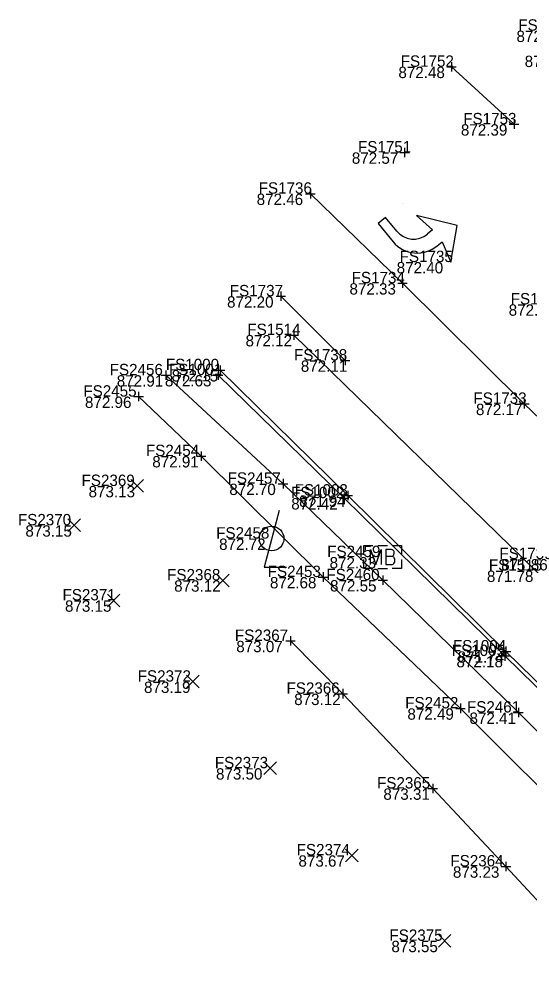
# Model space of a CAD drawing. Extents: x 1479420 to 1479833, y 379731 to 380103.
# Drawn here: x 1479444.2 to 1479498.2, y 379987.2 to 380088.3 of the extents above; entities that cross this region are included whole.
import ezdxf

# ---------------------------------------------------------------- set-up
doc = ezdxf.new("R2010")
doc.units = 0
for name, color, linetype in [('LT_X_Poles', 7, 'Continuous'), ('PM_X_Cells', 7, 'Continuous'), ('PM_X_Channelizing_Line', 7, 'Continuous'), ('PM_X_Lane_Line', 7, 'Continuous'), ('PV_X_Curb', 7, 'Continuous'), ('PV_X_Walk', 7, 'Continuous'), ('RD_X_Cells', 7, 'Continuous'), ('SV_X_Break_Lines', 7, 'Continuous'), ('SV_X_Random_Point', 7, 'Continuous'), ('SV_X_Shot_Marker', 7, 'Continuous'), ('SV_X_Text_Elevation', 7, 'Continuous'), ('SV_X_Text_Name', 7, 'Continuous'), ('UT_X_Water', 7, 'Continuous')]:
    doc.layers.add(name, color=color, linetype=linetype)

msp = doc.modelspace()

# ---------------------------------------------------------------- linework, layer by layer
at = {"layer": 'LT_X_Poles'}
msp.add_lwpolyline([(1479471.67, 380036.31), (1479470.09, 380030.33), (1479472.46, 380030.33)], dxfattribs=at)
msp.add_circle((1479470.88, 380033.36), 1.3, dxfattribs=at)
at = {"layer": 'PM_X_Cells'}
for p, q in [((1479484.71, 380068.78), (1479484.71, 380068.78)), ((1479482.91, 380067.3), (1479482.14, 380066.67)), ((1479484.09, 380065.86), (1479482.91, 380067.3)), ((1479490.48, 380066.48), (1479486.19, 380067.51)), ((1479486.19, 380067.51), (1479487.87, 380065.99)), ((1479482.14, 380066.67), (1479483.71, 380064.75)), ((1479489.79, 380062.6), (1479490.48, 380066.48)), ((1479487.87, 380065.99), (1479487.32, 380065.55)), ((1479488.37, 380064.33), (1479488.88, 380064.75)), ((1479488.88, 380064.75), (1479489.79, 380062.6)), ((1479489.79, 380062.6), (1479489.79, 380062.6))]:
    msp.add_line(p, q, dxfattribs=at)
for centre, radius, end in [((1479485.87, 380067.32), 2.3, 309.3649), ((1479486.25, 380066.83), 3.28, 310.2733)]:
    msp.add_arc(centre, radius, 219.3649, end, dxfattribs=at)
at = {"layer": 'PM_X_Channelizing_Line'}
msp.add_lwpolyline([(1479582.67, 379963.81), (1479570.27, 379976.46), (1479548.91, 379997.46), (1479531.64, 380014.2), (1479515.85, 380030.02), (1479497.57, 380047.61), (1479484.7, 380060.36), (1479474.97, 380069.83)], dxfattribs=at)
at = {"layer": 'PM_X_Lane_Line'}
for p, q in [((1479489.87, 380083.25), (1479496.48, 380077.17)), ((1479471.84, 380058.98), (1479478.64, 380052.19))]:
    msp.add_line(p, q, dxfattribs=at)
at = {"layer": 'PV_X_Curb'}
for points in [[(1479465.43, 380051.17), (1479478.92, 380037.91), (1479495.63, 380021.43), (1479511.64, 380005.78), (1479526.61, 379991.24), (1479541.43, 379976.72), (1479556.22, 379962.4), (1479558.52, 379960.09), (1479562.26, 379956.63), (1479564.94, 379953.17), (1479567.55, 379949.79), (1479570.39, 379944.78), (1479571.86, 379941.54), (1479572.44, 379940.29), (1479572.89, 379938.33), (1479573.21, 379936.75), (1479573.49, 379935.41), (1479573.82, 379931.24), (1479573.76, 379927.25), (1479573.04, 379921.89), (1479571.77, 379917.23), (1479569.5, 379912.16), (1479567.17, 379908.64), (1479563.94, 379905)], [(1479465.22, 380050.65), (1479478.53, 380037.63), (1479495.52, 380020.94), (1479511.46, 380005.33), (1479526.35, 379990.75), (1479540.93, 379976.57), (1479555.93, 379961.97), (1479555.89, 379961.63), (1479559.68, 379957.78), (1479564.54, 379952.78), (1479567.02, 379949.69), (1479570, 379944.36), (1479571.37, 379941.52), (1479571.64, 379940.63), (1479572.4, 379938.2), (1479572.73, 379936.74), (1479572.92, 379935.42), (1479573.29, 379931.12), (1479573.28, 379927.36), (1479572.59, 379922.13), (1479571.4, 379917.5), (1479569.16, 379912.51), (1479566.95, 379909.06), (1479563.85, 379905.52)]]:
    msp.add_lwpolyline(points, dxfattribs=at)
at = {"layer": 'PV_X_Walk'}
for points in [[(1479459.69, 380050.63), (1479472.08, 380039.16), (1479482.63, 380028.96), (1479496.94, 380014.96), (1479511.11, 380000.89), (1479521.78, 379990.32), (1479535.54, 379976.8), (1479546.78, 379965.86), (1479553.98, 379958.8), (1479560.12, 379952.43), (1479566.08, 379946.06), (1479567.84, 379944.16), (1479569.59, 379942.39), (1479571.25, 379941.41)], [(1479571.22, 379941.41), (1479571.44, 379940.74), (1479572.05, 379938.94), (1479572.4, 379937.36), (1479572.58, 379936.25), (1479572.71, 379935.62), (1479569.08, 379935.11), (1479567.56, 379937.2), (1479566.03, 379939.55), (1479564.62, 379941.63), (1479559.49, 379947.36), (1479553.28, 379954.09), (1479540.66, 379966.75), (1479530.12, 379977.06), (1479515.96, 379990.9), (1479504.53, 380001.71), (1479490.82, 380015.4), (1479476.31, 380029.29), (1479463.44, 380042.08), (1479456.83, 380048.37)]]:
    msp.add_lwpolyline(points, dxfattribs=at)
at = {"layer": 'RD_X_Cells'}
for p, q in [((1479482.09, 380032.62), (1479483.1, 380032.62)), ((1479482.61, 380031.4), (1479482.61, 380031.4)), ((1479482.09, 380030.18), (1479483.1, 380030.18))]:
    msp.add_line(p, q, dxfattribs=at)
for points in [[(1479480.61, 380031.65), (1479480.61, 380032.62), (1479481.58, 380032.62)], [(1479481.31, 380030.6), (1479481.31, 380032.2), (1479481.89, 380030.6), (1479482.44, 380032.2), (1479482.44, 380030.6)], [(1479483.63, 380031.47), (1479483.69, 380031.54), (1479483.73, 380031.57), (1479483.75, 380031.61), (1479483.77, 380031.64), (1479483.79, 380031.69), (1479483.8, 380031.72), (1479483.83, 380031.81), (1479483.83, 380031.85), (1479483.83, 380031.9), (1479483.82, 380031.98), (1479483.79, 380032.04), (1479483.75, 380032.09), (1479483.69, 380032.14), (1479483.64, 380032.17), (1479483.62, 380032.18), (1479483.55, 380032.2), (1479482.93, 380032.2), (1479482.93, 380030.6), (1479483.63, 380030.6), (1479483.72, 380030.65), (1479483.79, 380030.72), (1479483.85, 380030.82), (1479483.89, 380030.93), (1479483.9, 380031.04), (1479483.9, 380031.12), (1479483.88, 380031.2), (1479483.83, 380031.31), (1479483.77, 380031.38), (1479483.63, 380031.47), (1479482.93, 380031.47)], [(1479483.61, 380032.62), (1479484.61, 380032.62), (1479484.61, 380031.65)], [(1479481.58, 380030.18), (1479480.61, 380030.18), (1479480.61, 380031.15)], [(1479484.61, 380031.15), (1479484.61, 380030.18), (1479483.61, 380030.18)]]:
    msp.add_lwpolyline(points, dxfattribs=at)
at = {"layer": 'SV_X_Break_Lines'}
msp.add_lwpolyline([(1479534.39, 379905.65), (1479543.52, 379912.47), (1479551.34, 379918.19), (1479553.6, 379921.3), (1479553.86, 379925.5), (1479552.13, 379929.67), (1479547.93, 379935.99), (1479545.15, 379941.46), (1479539.82, 379948.42), (1479529.02, 379961.01), (1479520.63, 379970.73), (1479513.84, 379979.89), (1479504.81, 379988.78), (1479495.63, 379998.69), (1479487.89, 380006.93), (1479478.4, 380016.95), (1479472.87, 380022.54)], dxfattribs=at)
at = {"layer": 'SV_X_Random_Point'}
for p, q in [((1479456.02, 380038.26), (1479457.35, 380039.59)), ((1479456.02, 380039.59), (1479457.35, 380038.26)), ((1479449.35, 380034.09), (1479450.68, 380035.43)), ((1479449.35, 380035.43), (1479450.68, 380034.09)), ((1479465.06, 380028.27), (1479466.39, 380029.61)), ((1479465.06, 380029.61), (1479466.39, 380028.27)), ((1479453.53, 380026.15), (1479454.86, 380027.48)), ((1479453.53, 380027.48), (1479454.86, 380026.15)), ((1479461.89, 380017.56), (1479463.22, 380018.9)), ((1479461.89, 380018.9), (1479463.22, 380017.56)), ((1479470.06, 380008.41), (1479471.39, 380009.74)), ((1479470.06, 380009.74), (1479471.39, 380008.41)), ((1479478.69, 379999.19), (1479480.02, 380000.52)), ((1479478.69, 380000.52), (1479480.02, 379999.19)), ((1479488.49, 379990.15), (1479489.82, 379991.48)), ((1479488.49, 379991.48), (1479489.82, 379990.15))]:
    msp.add_line(p, q, dxfattribs=at)
at = {"layer": 'SV_X_Shot_Marker'}
for p, q in [((1479489.37, 380083.25), (1479490.37, 380083.25)), ((1479489.87, 380083.75), (1479489.87, 380082.75)), ((1479489.87, 380083.25), (1479489.87, 380083.25)), ((1479495.98, 380077.17), (1479496.98, 380077.17)), ((1479496.48, 380077.67), (1479496.48, 380076.67)), ((1479496.48, 380077.17), (1479496.48, 380077.17)), ((1479484.43, 380074.19), (1479485.43, 380074.19)), ((1479484.93, 380074.69), (1479484.93, 380073.69)), ((1479484.93, 380074.19), (1479484.93, 380074.19)), ((1479474.97, 380070.33), (1479474.97, 380069.33)), ((1479474.47, 380069.83), (1479475.47, 380069.83)), ((1479474.97, 380069.83), (1479474.97, 380069.83)), ((1479484.2, 380060.36), (1479485.2, 380060.36)), ((1479484.7, 380060.86), (1479484.7, 380059.86)), ((1479484.7, 380060.36), (1479484.7, 380060.36)), ((1479471.34, 380058.98), (1479472.34, 380058.98)), ((1479471.84, 380059.48), (1479471.84, 380058.48)), ((1479471.84, 380058.98), (1479471.84, 380058.98)), ((1479473.22, 380055.38), (1479473.22, 380054.38)), ((1479472.72, 380054.88), (1479473.72, 380054.88)), ((1479473.22, 380054.88), (1479473.22, 380054.88)), ((1479478.14, 380052.19), (1479479.14, 380052.19)), ((1479478.64, 380052.69), (1479478.64, 380051.69)), ((1479478.64, 380052.19), (1479478.64, 380052.19)), ((1479459.69, 380051.13), (1479459.69, 380050.13)), ((1479464.93, 380051.17), (1479465.93, 380051.17)), ((1479465.22, 380051.15), (1479465.22, 380050.15)), ((1479465.43, 380051.67), (1479465.43, 380050.67)), ((1479465.43, 380051.17), (1479465.43, 380051.17)), ((1479459.19, 380050.63), (1479460.19, 380050.63)), ((1479459.69, 380050.63), (1479459.69, 380050.63)), ((1479464.72, 380050.65), (1479465.72, 380050.65)), ((1479465.22, 380050.65), (1479465.22, 380050.65)), ((1479456.83, 380048.87), (1479456.83, 380047.87)), ((1479456.33, 380048.37), (1479457.33, 380048.37)), ((1479456.83, 380048.37), (1479456.83, 380048.37)), ((1479497.57, 380048.11), (1479497.57, 380047.11)), ((1479497.07, 380047.61), (1479498.07, 380047.61)), ((1479497.57, 380047.61), (1479497.57, 380047.61)), ((1479462.94, 380042.08), (1479463.94, 380042.08)), ((1479463.44, 380042.58), (1479463.44, 380041.58)), ((1479463.44, 380042.08), (1479463.44, 380042.08)), ((1479471.58, 380039.16), (1479472.58, 380039.16)), ((1479472.08, 380039.66), (1479472.08, 380038.66)), ((1479472.08, 380039.16), (1479472.08, 380039.16)), ((1479478.42, 380037.91), (1479479.42, 380037.91)), ((1479478.53, 380038.13), (1479478.53, 380037.13)), ((1479478.92, 380038.41), (1479478.92, 380037.41)), ((1479478.92, 380037.91), (1479478.92, 380037.91)), ((1479478.03, 380037.63), (1479479.03, 380037.63)), ((1479478.53, 380037.63), (1479478.53, 380037.63)), ((1479476.31, 380029.79), (1479476.31, 380028.79)), ((1479475.81, 380029.29), (1479476.81, 380029.29)), ((1479476.31, 380029.29), (1479476.31, 380029.29)), ((1479482.13, 380028.96), (1479483.13, 380028.96)), ((1479482.63, 380029.46), (1479482.63, 380028.46)), ((1479482.63, 380028.96), (1479482.63, 380028.96)), ((1479472.87, 380023.04), (1479472.87, 380022.04)), ((1479472.37, 380022.54), (1479473.37, 380022.54)), ((1479472.87, 380022.54), (1479472.87, 380022.54)), ((1479495.63, 380021.93), (1479495.63, 380020.93)), ((1479495.02, 380020.94), (1479496.02, 380020.94)), ((1479495.13, 380021.43), (1479496.13, 380021.43)), ((1479495.52, 380021.44), (1479495.52, 380020.44)), ((1479495.52, 380020.94), (1479495.52, 380020.94)), ((1479495.63, 380021.43), (1479495.63, 380021.43)), ((1479477.9, 380016.95), (1479478.9, 380016.95)), ((1479478.4, 380017.45), (1479478.4, 380016.45)), ((1479478.4, 380016.95), (1479478.4, 380016.95)), ((1479490.82, 380015.9), (1479490.82, 380014.9)), ((1479490.32, 380015.4), (1479491.32, 380015.4)), ((1479490.82, 380015.4), (1479490.82, 380015.4)), ((1479496.44, 380014.96), (1479497.44, 380014.96)), ((1479496.94, 380015.46), (1479496.94, 380014.46)), ((1479496.94, 380014.96), (1479496.94, 380014.96)), ((1479487.89, 380007.43), (1479487.89, 380006.43)), ((1479487.39, 380006.93), (1479488.39, 380006.93)), ((1479487.89, 380006.93), (1479487.89, 380006.93)), ((1479495.13, 379998.69), (1479496.13, 379998.69)), ((1479495.63, 379999.19), (1479495.63, 379998.19)), ((1479495.63, 379998.69), (1479495.63, 379998.69))]:
    msp.add_line(p, q, dxfattribs=at)
at = {"layer": 'UT_X_Water'}
msp.add_lwpolyline([(1479473.22, 380054.88), (1479498.74, 380029.97), (1479514.5, 380014.09), (1479533.45, 379996.74), (1479556, 379974.32), (1479574.86, 379956.27), (1479584.4, 379947.43), (1479599.6, 379932.82), (1479630.11, 379903.78), (1479644.77, 379889.72), (1479654.21, 379882.36), (1479664.27, 379872.63), (1479692.51, 379845.85), (1479712.67, 379826.69), (1479730.74, 379809.85), (1479753.15, 379788.31), (1479771.84, 379770.54), (1479781.68, 379761.1)], dxfattribs=at)

# ---------------------------------------------------------------- texts
at = {"layer": 'SV_X_Text_Elevation'}
for s, p in [('872.48', (1479496.74, 380085.87)), ('872.29', (1479497.61, 380083.22)), ('872.48', (1479484.27, 380082.05)), ('872.39', (1479490.87, 380075.97)), ('872.57', (1479479.35, 380072.99)), ('872.46', (1479469.3, 380068.63)), ('872.40', (1479484.09, 380061.4)), ('872.33', (1479479.1, 380059.16)), ('872.20', (1479466.17, 380057.78)), ('872.36', (1479495.92, 380056.92)), ('872.12', (1479468.12, 380053.68)), ('872.11', (1479473.96, 380050.99)), ('872.15', (1479460.32, 380049.97)), ('872.91', (1479454.52, 380049.43)), ('872.63', (1479459.61, 380049.45)), ('872.96', (1479451.16, 380047.17)), ('872.17', (1479492.46, 380046.41)), ('872.91', (1479458.27, 380040.88)), ('873.13', (1479451.54, 380037.72)), ('872.70', (1479466.41, 380037.96)), ('871.94', (1479473.78, 380036.71)), ('872.42', (1479472.95, 380036.43)), ('873.15', (1479444.87, 380033.56)), ('872.72', (1479465.33, 380032.16)), ('872.33', (1479477, 380030.2)), ('871.86', (1479495.13, 380029.99)), ('871.78', (1479493.62, 380028.77)), ('873.12', (1479460.58, 380027.74)), ('872.68', (1479470.7, 380028.09)), ('872.55', (1479477.05, 380027.76)), ('873.15', (1479449.05, 380025.62)), ('873.07', (1479467.14, 380021.34)), ('872.18', (1479490.4, 380019.74)), ('871.74', (1479490.53, 380020.23)), ('873.19', (1479457.4, 380017.03)), ('873.12', (1479473.26, 380015.75)), ('872.49', (1479485.22, 380014.2)), ('872.41', (1479491.78, 380013.76)), ('873.50', (1479465, 380007.87)), ('873.31', (1479482.68, 380005.73)), ('873.67', (1479473.71, 379998.66)), ('873.23', (1479490.03, 379997.49)), ('873.55', (1479483.53, 379989.62))]:
    msp.add_text(s, height=1.2, dxfattribs=at).set_placement(p)
at = {"layer": 'SV_X_Text_Name'}
for s, p in [('FS1593', (1479496.93, 380087.07)), ('FS1752', (1479484.51, 380083.25)), ('FS1753', (1479491.12, 380077.17)), ('FS1751', (1479480, 380074.19)), ('FS1736', (1479469.51, 380069.83)), ('FS1735', (1479484.4, 380062.6)), ('FS1734', (1479479.33, 380060.36)), ('FS1737', (1479466.46, 380058.98)), ('FS1750', (1479496.13, 380058.12)), ('FS1514', (1479468.31, 380054.88)), ('FS1738', (1479473.24, 380052.19)), ('FS1000', (1479459.71, 380051.17)), ('FS2456', (1479453.77, 380050.63)), ('FS1001', (1479460.04, 380050.65)), ('FS2455', (1479450.99, 380048.37)), ('FS1733', (1479492.19, 380047.61)), ('FS2454', (1479457.6, 380042.08)), ('FS2369', (1479450.8, 380038.92)), ('FS2457', (1479466.23, 380039.16)), ('FS1002', (1479472.93, 380037.63)), ('FS1003', (1479473.31, 380037.91)), ('FS2370', (1479444.08, 380034.76)), ('FS2458', (1479465.02, 380033.36)), ('FS2459', (1479476.75, 380031.4)), ('FS1739', (1479494.94, 380031.19)), ('FS1515', (1479493.83, 380029.97)), ('FS2368', (1479459.84, 380028.94)), ('FS2453', (1479470.46, 380029.29)), ('FS2460', (1479476.66, 380028.96)), ('FS2371', (1479448.79, 380026.82)), ('FS2367', (1479467, 380022.54)), ('FS1004', (1479490.03, 380021.43)), ('FS1005', (1479489.91, 380020.94)), ('FS2372', (1479456.73, 380018.23)), ('FS2366', (1479472.45, 380016.95)), ('FS2452', (1479484.99, 380015.4)), ('FS2461', (1479491.51, 380014.96)), ('FS2373', (1479464.88, 380009.07)), ('FS2365', (1479482.01, 380006.93)), ('FS2374', (1479473.52, 379999.86)), ('FS2364', (1479489.76, 379998.69)), ('FS2375', (1479483.32, 379990.82))]:
    msp.add_text(s, height=1.2, dxfattribs=at).set_placement(p)

doc.saveas('drawing.dxf')
